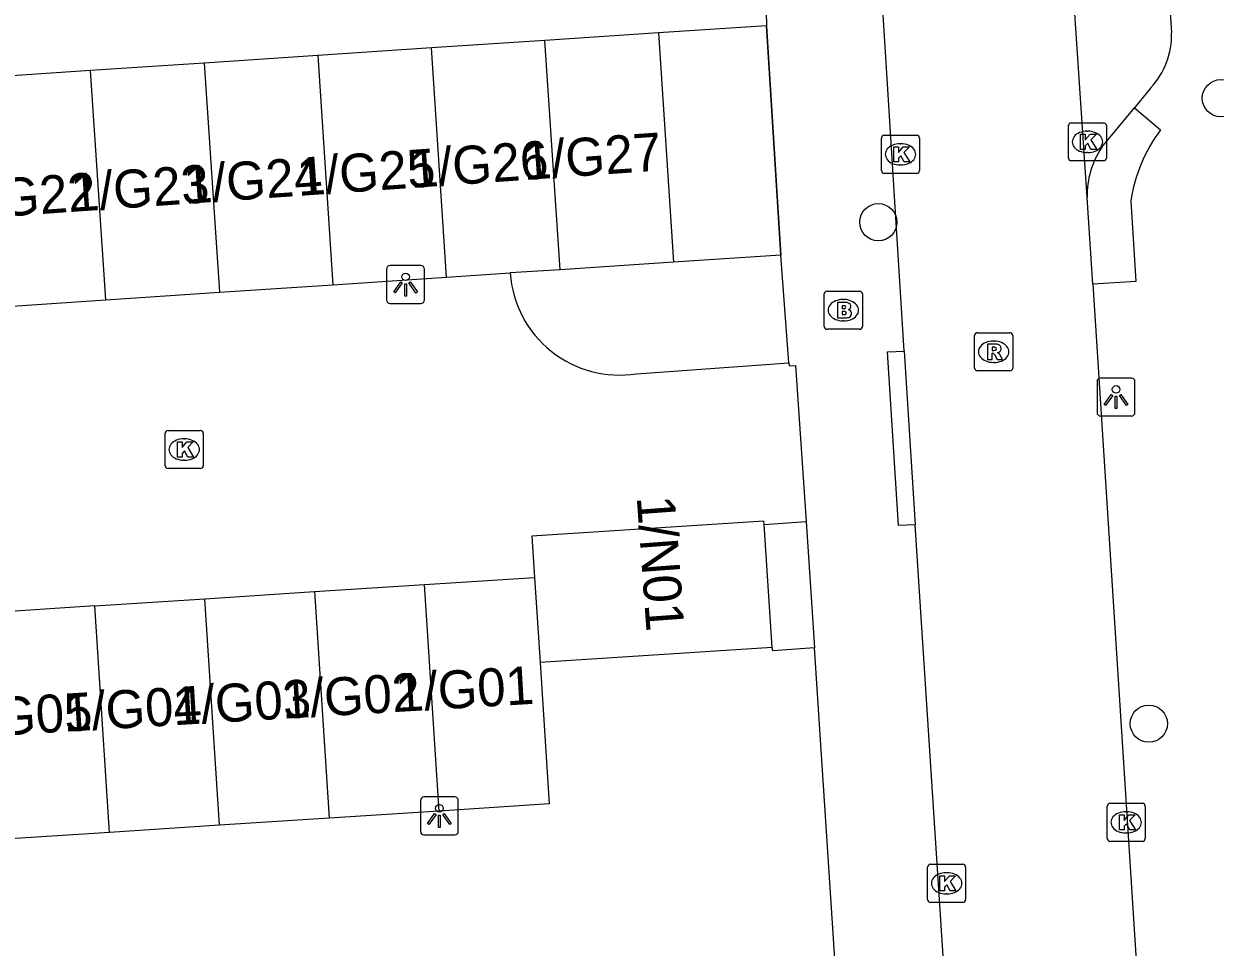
# Model space of a CAD drawing. Extents: x 159689 to 160786, y 387323 to 388339.
# Drawn here: x 160323.26 to 160354.58, y 388061.5 to 388085.77 of the extents above; entities that cross this region are included whole.
import ezdxf

# ---------------------------------------------------------------- set-up
doc = ezdxf.new("R2010")
doc.units = 0
for name, color, linetype in [('IMGEO_Boom', 7, 'Continuous'), ('IMGEO_Brandkraan', 7, 'Continuous'), ('IMGEO_Hek', 7, 'Continuous'), ('IMGEO_Kolk', 7, 'Continuous'), ('IMGEO_Lichtpunt', 7, 'Continuous'), ('IMGEO_Muur', 7, 'Continuous'), ('IMGEO_Pand', 7, 'Continuous'), ('IMGEO_Pand_nummerreeks', 7, 'Continuous'), ('IMGEO_Rijbaan_lokaal_open', 7, 'Continuous'), ('IMGEO_Rioolput', 7, 'Continuous'), ('IMGEO_Voetpad_open', 7, 'Continuous')]:
    doc.layers.add(name, color=color, linetype=linetype)

msp = doc.modelspace()

# ---------------------------------------------------------------- linework, layer by layer
at = {"layer": 'IMGEO_Boom'}
for centre in [(160354.735, 388083.812), (160345.727, 388080.553), (160352.84, 388067.377)]:
    msp.add_circle(centre, 0.489, dxfattribs=at)
at = {"layer": 'IMGEO_Brandkraan'}
for p, q in [((160344.382, 388078.741), (160345.234, 388078.741)), ((160344.307, 388077.815), (160344.307, 388078.667)), ((160344.795, 388078.521), (160344.82, 388078.521)), ((160345.308, 388078.667), (160345.308, 388077.815)), ((160344.818, 388077.961), (160344.793, 388077.961)), ((160345.234, 388077.741), (160344.382, 388077.741))]:
    msp.add_line(p, q, dxfattribs=at)
for points in [[(160344.382, 388078.741), (160345.234, 388078.741)], [(160344.307, 388077.815), (160344.307, 388078.667)], [(160344.655, 388078.441), (160344.655, 388078.041), (160344.868, 388078.041)], [(160344.886, 388078.441), (160344.655, 388078.441)], [(160345.308, 388078.667), (160345.308, 388077.815)], [(160344.834, 388078.36), (160344.78, 388078.36), (160344.78, 388078.284)], [(160344.78, 388078.284), (160344.833, 388078.284)], [(160344.842, 388078.208), (160344.78, 388078.208), (160344.78, 388078.127)], [(160344.78, 388078.127), (160344.842, 388078.127)], [(160345.234, 388077.741), (160344.382, 388077.741)]]:
    msp.add_lwpolyline(points, dxfattribs=at)
for centre, radius, start, end in [((160344.384, 388078.665), 0.0765, 91.552, 178.448), ((160344.384, 388078.665), 0.0765, 91.552, 178.448), ((160345.232, 388078.665), 0.0765, 1.552, 88.448), ((160345.232, 388078.665), 0.0765, 1.552, 88.448), ((160344.89, 388078.296), 0.145, 59.4692, 91.5367), ((160344.915, 388078.343), 0.0922, 285.5137, 58.1501), ((160344.835, 388078.322), 0.0379, 267.8285, 90.9355), ((160344.843, 388078.167), 0.0404, 269.8759, 90.5077), ((160344.92, 388078.151), 0.105, 301.3115, 78.989), ((160344.384, 388077.817), 0.0765, 181.552, 268.448), ((160344.384, 388077.817), 0.0765, 181.552, 268.448), ((160344.874, 388078.292), 0.251, 268.6676, 293.5347), ((160345.232, 388077.817), 0.0765, 271.552, 358.448), ((160345.232, 388077.817), 0.0765, 271.552, 358.448)]:
    msp.add_arc(centre, radius, start, end, dxfattribs=at)
for centre, major_axis, ratio, start_param, end_param in [((160344.794, 388078.241), (-0.387, 0.002), 0.722429, 4.712389, 7.853982), ((160344.819, 388078.241), (-0.39, 0.002), 0.717154, 1.570796, 4.712389)]:
    msp.add_ellipse(centre, major_axis=major_axis, ratio=ratio, start_param=start_param, end_param=end_param, dxfattribs=at)
at = {"layer": 'IMGEO_Hek'}
msp.add_lwpolyline([(160345.247, 388051.01), (160344.051, 388069.366)], dxfattribs=at)
at = {"layer": 'IMGEO_Kolk'}
for p, q in [((160350.801, 388083.165), (160351.653, 388083.165)), ((160345.885, 388082.837), (160346.737, 388082.837)), ((160350.726, 388082.239), (160350.726, 388083.091)), ((160351.214, 388082.945), (160351.239, 388082.945)), ((160351.727, 388083.091), (160351.727, 388082.239)), ((160345.81, 388081.911), (160345.81, 388082.763)), ((160346.298, 388082.617), (160346.323, 388082.617)), ((160346.811, 388082.763), (160346.811, 388081.911)), ((160351.237, 388082.385), (160351.212, 388082.385)), ((160346.321, 388082.057), (160346.296, 388082.057)), ((160351.653, 388082.165), (160350.801, 388082.165)), ((160346.737, 388081.837), (160345.885, 388081.837)), ((160326.975, 388074.154), (160326.975, 388075.006)), ((160327.05, 388075.08), (160327.902, 388075.08)), ((160327.976, 388075.006), (160327.976, 388074.154)), ((160327.463, 388074.86), (160327.488, 388074.86)), ((160327.902, 388074.08), (160327.05, 388074.08)), ((160327.486, 388074.3), (160327.461, 388074.3)), ((160351.819, 388065.282), (160352.671, 388065.282)), ((160351.744, 388064.356), (160351.744, 388065.208)), ((160352.232, 388065.062), (160352.257, 388065.062)), ((160352.745, 388065.208), (160352.745, 388064.356)), ((160352.255, 388064.502), (160352.23, 388064.502)), ((160352.671, 388064.282), (160351.819, 388064.282)), ((160347.022, 388062.754), (160347.022, 388063.606)), ((160347.097, 388063.68), (160347.949, 388063.68)), ((160347.51, 388063.46), (160347.535, 388063.46)), ((160348.023, 388063.606), (160348.023, 388062.754)), ((160347.533, 388062.9), (160347.508, 388062.9)), ((160347.949, 388062.68), (160347.097, 388062.68))]:
    msp.add_line(p, q, dxfattribs=at)
for points in [[(160350.801, 388083.165), (160351.653, 388083.165)], [(160345.885, 388082.837), (160346.737, 388082.837)], [(160350.726, 388082.239), (160350.726, 388083.091)], [(160351.047, 388082.865), (160351.17, 388082.865), (160351.17, 388082.714), (160351.3, 388082.865), (160351.464, 388082.865), (160351.318, 388082.714), (160351.471, 388082.465), (160351.319, 388082.465), (160351.234, 388082.629), (160351.17, 388082.562), (160351.17, 388082.465), (160351.047, 388082.465), (160351.047, 388082.865)], [(160351.727, 388083.091), (160351.727, 388082.239)], [(160345.81, 388081.911), (160345.81, 388082.763)], [(160346.131, 388082.537), (160346.254, 388082.537), (160346.254, 388082.386), (160346.384, 388082.537), (160346.548, 388082.537), (160346.402, 388082.386), (160346.555, 388082.137), (160346.403, 388082.137), (160346.318, 388082.301), (160346.254, 388082.234), (160346.254, 388082.137), (160346.131, 388082.137), (160346.131, 388082.537)], [(160346.811, 388082.763), (160346.811, 388081.911)], [(160351.653, 388082.165), (160350.801, 388082.165)], [(160346.737, 388081.837), (160345.885, 388081.837)], [(160326.975, 388074.154), (160326.975, 388075.006)], [(160327.05, 388075.08), (160327.902, 388075.08)], [(160327.976, 388075.006), (160327.976, 388074.154)], [(160327.296, 388074.78), (160327.419, 388074.78), (160327.419, 388074.629), (160327.549, 388074.78), (160327.713, 388074.78), (160327.567, 388074.629), (160327.72, 388074.38), (160327.568, 388074.38), (160327.483, 388074.544), (160327.419, 388074.477), (160327.419, 388074.38), (160327.296, 388074.38), (160327.296, 388074.78)], [(160327.902, 388074.08), (160327.05, 388074.08)], [(160351.819, 388065.282), (160352.671, 388065.282)], [(160351.744, 388064.356), (160351.744, 388065.208)], [(160352.065, 388064.982), (160352.188, 388064.982), (160352.188, 388064.831), (160352.318, 388064.982), (160352.482, 388064.982), (160352.336, 388064.831), (160352.489, 388064.582), (160352.337, 388064.582), (160352.252, 388064.746), (160352.188, 388064.679), (160352.188, 388064.582), (160352.065, 388064.582), (160352.065, 388064.982)], [(160352.745, 388065.208), (160352.745, 388064.356)], [(160352.671, 388064.282), (160351.819, 388064.282)], [(160347.022, 388062.754), (160347.022, 388063.606)], [(160347.097, 388063.68), (160347.949, 388063.68)], [(160347.343, 388063.38), (160347.466, 388063.38), (160347.466, 388063.229), (160347.596, 388063.38), (160347.76, 388063.38), (160347.614, 388063.229), (160347.767, 388062.98), (160347.615, 388062.98), (160347.53, 388063.144), (160347.466, 388063.077), (160347.466, 388062.98), (160347.343, 388062.98), (160347.343, 388063.38)], [(160348.023, 388063.606), (160348.023, 388062.754)], [(160347.949, 388062.68), (160347.097, 388062.68)]]:
    msp.add_lwpolyline(points, dxfattribs=at)
for centre, start, end in [((160350.803, 388083.089), 91.552, 178.448), ((160350.803, 388083.089), 91.552, 178.448), ((160351.651, 388083.089), 1.552, 88.448), ((160351.651, 388083.089), 1.552, 88.448), ((160345.887, 388082.761), 91.552, 178.448), ((160345.887, 388082.761), 91.552, 178.448), ((160346.735, 388082.761), 1.552, 88.448), ((160346.735, 388082.761), 1.552, 88.448), ((160350.803, 388082.241), 181.552, 268.448), ((160350.803, 388082.241), 181.552, 268.448), ((160351.651, 388082.241), 271.552, 358.448), ((160351.651, 388082.241), 271.552, 358.448), ((160345.887, 388081.913), 181.552, 268.448), ((160345.887, 388081.913), 181.552, 268.448), ((160346.735, 388081.913), 271.552, 358.448), ((160346.735, 388081.913), 271.552, 358.448), ((160327.052, 388075.004), 91.552, 178.448), ((160327.052, 388075.004), 91.552, 178.448), ((160327.9, 388075.004), 1.552, 88.448), ((160327.9, 388075.004), 1.552, 88.448), ((160327.052, 388074.156), 181.552, 268.448), ((160327.052, 388074.156), 181.552, 268.448), ((160327.9, 388074.156), 271.552, 358.448), ((160327.9, 388074.156), 271.552, 358.448), ((160351.821, 388065.206), 91.552, 178.448), ((160351.821, 388065.206), 91.552, 178.448), ((160352.669, 388065.206), 1.552, 88.448), ((160352.669, 388065.206), 1.552, 88.448), ((160351.821, 388064.358), 181.552, 268.448), ((160351.821, 388064.358), 181.552, 268.448), ((160352.669, 388064.358), 271.552, 358.448), ((160352.669, 388064.358), 271.552, 358.448), ((160347.099, 388063.604), 91.552, 178.448), ((160347.099, 388063.604), 91.552, 178.448), ((160347.947, 388063.604), 1.552, 88.448), ((160347.947, 388063.604), 1.552, 88.448), ((160347.099, 388062.756), 181.552, 268.448), ((160347.099, 388062.756), 181.552, 268.448), ((160347.947, 388062.756), 271.552, 358.448), ((160347.947, 388062.756), 271.552, 358.448)]:
    msp.add_arc(centre, 0.0765, start, end, dxfattribs=at)
for centre, major_axis, ratio, start_param, end_param in [((160351.213, 388082.665), (-0.387, 0.002), 0.722429, 4.712389, 7.853982), ((160351.238, 388082.665), (-0.39, 0.002), 0.717154, 1.570796, 4.712389), ((160346.297, 388082.337), (-0.387, 0.002), 0.722429, 4.712389, 7.853982), ((160346.322, 388082.337), (-0.39, 0.002), 0.717154, 1.570796, 4.712389), ((160327.462, 388074.58), (-0.387, 0.002), 0.722429, 4.712389, 7.853982), ((160327.487, 388074.58), (-0.39, 0.002), 0.717154, 1.570796, 4.712389), ((160352.231, 388064.782), (-0.387, 0.002), 0.722429, 4.712389, 7.853982), ((160352.256, 388064.782), (-0.39, 0.002), 0.717154, 1.570796, 4.712389), ((160347.509, 388063.18), (-0.387, 0.002), 0.722429, 4.712389, 7.853982), ((160347.534, 388063.18), (-0.39, 0.002), 0.717154, 1.570796, 4.712389)]:
    msp.add_ellipse(centre, major_axis=major_axis, ratio=ratio, start_param=start_param, end_param=end_param, dxfattribs=at)
at = {"layer": 'IMGEO_Lichtpunt'}
for p, q in [((160333.699, 388079.415), (160332.891, 388079.415)), ((160333.699, 388079.415), (160332.891, 388079.415)), ((160332.797, 388079.32), (160332.797, 388078.513)), ((160332.797, 388079.32), (160332.797, 388078.513)), ((160333.793, 388078.513), (160333.793, 388079.32)), ((160333.793, 388078.513), (160333.793, 388079.32)), ((160332.891, 388078.419), (160333.699, 388078.419)), ((160332.891, 388078.419), (160333.699, 388078.419)), ((160351.479, 388076.362), (160351.479, 388075.555)), ((160351.479, 388076.362), (160351.479, 388075.555)), ((160352.381, 388076.457), (160351.573, 388076.457)), ((160352.381, 388076.457), (160351.573, 388076.457)), ((160352.475, 388075.555), (160352.475, 388076.362)), ((160352.475, 388075.555), (160352.475, 388076.362)), ((160351.573, 388075.461), (160352.381, 388075.461)), ((160351.573, 388075.461), (160352.381, 388075.461)), ((160333.687, 388065.354), (160333.687, 388064.547)), ((160333.687, 388065.354), (160333.687, 388064.547)), ((160334.589, 388065.449), (160333.781, 388065.449)), ((160334.589, 388065.449), (160333.781, 388065.449)), ((160334.683, 388064.547), (160334.683, 388065.354)), ((160334.683, 388064.547), (160334.683, 388065.354)), ((160333.781, 388064.453), (160334.589, 388064.453)), ((160333.781, 388064.453), (160334.589, 388064.453))]:
    msp.add_line(p, q, dxfattribs=at)
for points in [[(160333.171, 388078.984), (160333.21, 388078.956), (160333.022, 388078.694), (160332.984, 388078.721), (160333.171, 388078.984)], [(160333.273, 388078.936), (160333.32, 388078.936), (160333.32, 388078.614), (160333.273, 388078.614), (160333.273, 388078.936)], [(160333.383, 388078.956), (160333.421, 388078.983), (160333.608, 388078.721), (160333.569, 388078.693), (160333.383, 388078.956)], [(160351.853, 388076.026), (160351.892, 388075.998), (160351.704, 388075.736), (160351.666, 388075.763), (160351.853, 388076.026)], [(160351.955, 388075.978), (160352.002, 388075.978), (160352.002, 388075.656), (160351.955, 388075.656), (160351.955, 388075.978)], [(160352.065, 388075.998), (160352.103, 388076.025), (160352.29, 388075.763), (160352.251, 388075.735), (160352.065, 388075.998)], [(160334.061, 388065.018), (160334.1, 388064.99), (160333.912, 388064.728), (160333.874, 388064.755), (160334.061, 388065.018)], [(160334.163, 388064.97), (160334.21, 388064.97), (160334.21, 388064.648), (160334.163, 388064.648), (160334.163, 388064.97)], [(160334.273, 388064.99), (160334.311, 388065.017), (160334.498, 388064.755), (160334.459, 388064.727), (160334.273, 388064.99)]]:
    msp.add_lwpolyline(points, dxfattribs=at)
for centre in [(160333.296, 388079.118), (160351.978, 388076.16), (160334.186, 388065.152)]:
    msp.add_circle(centre, 0.0994, dxfattribs=at)
for centre, start, end in [((160332.891, 388079.32), 90, 180), ((160332.891, 388079.32), 90, 180), ((160333.699, 388079.32), 0, 90), ((160333.699, 388079.32), 0, 90), ((160332.891, 388078.513), 180, 270), ((160332.891, 388078.513), 180, 270), ((160333.699, 388078.513), 270, 0), ((160333.699, 388078.513), 270, 360), ((160351.573, 388076.362), 90, 180), ((160351.573, 388076.362), 90, 180), ((160352.381, 388076.362), 0, 90), ((160352.381, 388076.362), 0, 90), ((160351.573, 388075.555), 180, 270), ((160351.573, 388075.555), 180, 270), ((160352.381, 388075.555), 270, 0), ((160352.381, 388075.555), 270, 360), ((160333.781, 388065.354), 90, 180), ((160333.781, 388065.354), 90, 180), ((160334.589, 388065.354), 0, 90), ((160334.589, 388065.354), 0, 90), ((160333.781, 388064.547), 180, 270), ((160333.781, 388064.547), 180, 270), ((160334.589, 388064.547), 270, 0), ((160334.589, 388064.547), 270, 360)]:
    msp.add_arc(centre, 0.0946, start, end, dxfattribs=at)
at = {"layer": 'IMGEO_Muur'}
for points in [[(160342.783, 388085.715), (160343.168, 388079.685)], [(160343.168, 388079.685), (160340.346, 388079.504)]]:
    msp.add_lwpolyline(points, dxfattribs=at)
at = {"layer": 'IMGEO_Pand'}
for points in [[(160336.96, 388085.331), (160333.974, 388085.132)], [(160339.946, 388085.529), (160336.96, 388085.331)], [(160337.36, 388079.306), (160336.96, 388085.331)], [(160339.946, 388085.529), (160340.346, 388079.504)], [(160333.974, 388085.132), (160330.988, 388084.934)], [(160334.374, 388079.108), (160333.974, 388085.132)], [(160328.002, 388084.736), (160325.016, 388084.537)], [(160330.988, 388084.934), (160328.002, 388084.736)], [(160328.002, 388084.736), (160328.402, 388078.711)], [(160330.988, 388084.934), (160331.388, 388078.909)], [(160325.016, 388084.537), (160322.03, 388084.339)], [(160325.416, 388078.513), (160325.016, 388084.537)], [(160340.346, 388079.504), (160337.36, 388079.306)], [(160331.388, 388078.909), (160334.374, 388079.108)], [(160334.374, 388079.108), (160336.048, 388079.219)], [(160337.36, 388079.306), (160336.048, 388079.219)], [(160328.402, 388078.711), (160331.388, 388078.909)], [(160322.43, 388078.314), (160325.416, 388078.513)], [(160325.416, 388078.513), (160328.402, 388078.711)], [(160342.725, 388072.61), (160342.719, 388072.7), (160336.615, 388072.304), (160336.686, 388071.221)], [(160342.935, 388069.379), (160342.725, 388072.61)], [(160333.795, 388071.033), (160336.686, 388071.221)], [(160336.686, 388071.221), (160336.833, 388068.983)], [(160330.905, 388070.846), (160333.795, 388071.033)], [(160334.182, 388065.08), (160333.795, 388071.033)], [(160325.123, 388070.471), (160328.014, 388070.658)], [(160328.014, 388070.658), (160330.905, 388070.846)], [(160328.4, 388064.705), (160328.014, 388070.658)], [(160330.905, 388070.846), (160331.291, 388064.893)], [(160325.123, 388070.471), (160322.233, 388070.283)], [(160325.509, 388064.517), (160325.123, 388070.471)], [(160342.935, 388069.379), (160336.833, 388068.983)], [(160336.833, 388068.983), (160337.074, 388065.268), (160334.182, 388065.08)], [(160334.182, 388065.08), (160331.291, 388064.893)], [(160328.4, 388064.705), (160325.509, 388064.517)], [(160331.291, 388064.893), (160328.4, 388064.705)], [(160325.509, 388064.517), (160322.619, 388064.33)]]:
    msp.add_lwpolyline(points, dxfattribs=at)
at = {"layer": 'IMGEO_Rijbaan_lokaal_open'}
for points in [[(160351.221, 388081.202), (160349.405, 388108.263)], [(160346.407, 388077.164), (160344.486, 388107.928)], [(160351.366, 388078.927), (160351.221, 388081.202)], [(160351.366, 388078.927), (160352.685, 388058.42)], [(160346.407, 388077.164), (160346.697, 388072.604)], [(160339.372, 388076.57), (160343.378, 388076.862)], [(160343.378, 388076.862), (160343.384, 388076.781), (160343.554, 388076.791), (160343.833, 388072.688)], [(160342.725, 388072.61), (160343.833, 388072.688)], [(160347.63, 388058.162), (160346.697, 388072.604)]]:
    msp.add_lwpolyline(points, dxfattribs=at)
msp.add_arc((160338.923, 388079.417), 2.882, 183.9346, 278.9605, dxfattribs=at)
at = {"layer": 'IMGEO_Rioolput'}
for p, q in [((160348.26, 388076.722), (160348.26, 388077.574)), ((160348.335, 388077.648), (160349.187, 388077.648)), ((160349.261, 388077.574), (160349.261, 388076.722)), ((160348.748, 388077.428), (160348.773, 388077.428)), ((160348.771, 388076.868), (160348.746, 388076.868)), ((160349.187, 388076.648), (160348.335, 388076.648))]:
    msp.add_line(p, q, dxfattribs=at)
for points in [[(160348.26, 388076.722), (160348.26, 388077.574)], [(160348.335, 388077.648), (160349.187, 388077.648)], [(160349.261, 388077.574), (160349.261, 388076.722)], [(160348.849, 388077.346), (160348.597, 388077.348), (160348.597, 388076.948)], [(160348.775, 388077.267), (160348.721, 388077.267), (160348.721, 388077.186)], [(160348.721, 388077.186), (160348.773, 388077.186)], [(160348.597, 388076.948), (160348.721, 388076.948), (160348.721, 388077.11), (160348.732, 388077.11)], [(160348.779, 388077.081), (160348.85, 388076.948), (160348.99, 388076.948), (160348.925, 388077.074)], [(160349.187, 388076.648), (160348.335, 388076.648)]]:
    msp.add_lwpolyline(points, dxfattribs=at)
for centre, radius, start, end in [((160348.337, 388077.572), 0.0765, 91.552, 178.448), ((160348.337, 388077.572), 0.0765, 91.552, 178.448), ((160349.185, 388077.572), 0.0765, 1.552, 88.448), ((160349.185, 388077.572), 0.0765, 1.552, 88.448), ((160348.757, 388077.375), 0.19, 274.7715, 282.9687), ((160348.781, 388077.171), 0.0964, 77.0061, 93.1865), ((160348.795, 388077.228), 0.0378, 276.6634, 79.6772), ((160348.848, 388077.236), 0.109, 350.3612, 89.416), ((160348.846, 388077.236), 0.112, 277.5842, 350.9817), ((160348.731, 388077.057), 0.0533, 26.0293, 88.6989), ((160348.83, 388077.021), 0.108, 29.5134, 73.7905), ((160348.337, 388076.724), 0.0765, 181.552, 268.448), ((160348.337, 388076.724), 0.0765, 181.552, 268.448), ((160349.185, 388076.724), 0.0765, 271.552, 358.448), ((160349.185, 388076.724), 0.0765, 271.552, 358.448)]:
    msp.add_arc(centre, radius, start, end, dxfattribs=at)
for centre, major_axis, ratio, start_param, end_param in [((160348.747, 388077.148), (-0.387, 0.002), 0.722429, 4.712389, 7.853982), ((160348.772, 388077.148), (-0.39, 0.002), 0.717154, 1.570796, 4.712389)]:
    msp.add_ellipse(centre, major_axis=major_axis, ratio=ratio, start_param=start_param, end_param=end_param, dxfattribs=at)
at = {"layer": 'IMGEO_Voetpad_open'}
for points in [[(160349.992, 388138.56), (160353.439, 388085.533)], [(160342.749, 388087.181), (160342.783, 388085.715)], [(160342.783, 388085.715), (160339.946, 388085.529)], [(160343.168, 388079.685), (160342.783, 388085.715)], [(160352.886, 388084.079), (160352.463, 388083.562)], [(160351.608, 388082.525), (160352.463, 388083.562)], [(160352.463, 388083.562), (160353.149, 388082.978)], [(160352.368, 388081.105), (160352.5, 388078.999), (160351.366, 388078.927)], [(160343.168, 388079.685), (160340.346, 388079.504)], [(160343.378, 388076.862), (160343.168, 388079.685)], [(160346.697, 388072.604), (160346.258, 388072.58), (160345.967, 388077.145), (160346.407, 388077.164)], [(160343.833, 388072.688), (160344.051, 388069.366)], [(160344.051, 388069.366), (160342.956, 388069.292), (160342.935, 388069.379)], [(160345.786, 388042.758), (160345.247, 388051.01), (160344.051, 388069.366)]]:
    msp.add_lwpolyline(points, dxfattribs=at)
for centre, radius, start, end in [((160351.395, 388085.478), 2.045, 316.8236, 1.5297), ((160356.399, 388080.524), 4.073, 142.938, 171.7919), ((160353.438, 388081.272), 2.218, 145.5882, 181.8016)]:
    msp.add_arc(centre, radius, start, end, dxfattribs=at)

# ---------------------------------------------------------------- texts
at = {"layer": 'IMGEO_Pand_nummerreeks'}
for s, rotation, p in [('1/G27', 4.0263, (160336.419, 388081.661)), ('1/G25', 4.0263, (160330.474, 388081.243)), ('1/G26', 4.0263, (160333.446, 388081.452)), ('1/G24', 4.0263, (160327.501, 388081.034)), ('1/G22', 4.0263, (160321.55, 388080.615)), ('1/G23', 4.0263, (160324.529, 388080.824)), ('1/N01', 274.1909, (160339.373, 388073.332)), ('1/G02', 3.4028, (160330.068, 388067.504)), ('1/G01', 3.4028, (160333.059, 388067.682)), ('1/G03', 3.4028, (160327.199, 388067.333)), ('1/G05', 3.4028, (160321.449, 388066.991)), ('1/G04', 3.4028, (160324.324, 388067.162))]:
    msp.add_text(s, height=1, rotation=rotation, dxfattribs=at).set_placement(p)

doc.saveas('drawing.dxf')
